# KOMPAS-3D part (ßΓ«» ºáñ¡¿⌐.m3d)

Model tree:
1. Эскиз:1
2. Операция выдавливания:1
     Расстояние 1 = 4.2; Расстояние 2 = 1.6
3. Эскиз:2
4. Операция выдавливания:2
     Расстояние 1 = 0.5; Расстояние 2 = 1.6
5. Эскиз:3
6. Операция выдавливания:6
     Расстояние 1 = 0.1; Расстояние 2 = 2.4
7. Эскиз:7
8. Операция выдавливания:7
     Расстояние 1 = 0.5; Расстояние 2 = 2.4
9. Эскиз:8
10. Операция выдавливания:8
     Расстояние 1 = 4; Расстояние 2 = 2.4
11. Эскиз:9
12. Операция выдавливания:9
     Расстояние 1 = 5; Расстояние 2 = 2.4
13. Скругление:5
     Радиус = 1.5
14. Скругление:6
     Радиус = 0.2
15. Эскиз:10
16. Операция выдавливания:10
     Расстояние 1 = 5; Расстояние 2 = 2
17. Эскиз:11
18. Вырезать элемент выдавливания:2
     Расстояние 1 = 0.5
19. Эскиз:12
20. Операция выдавливания:11
     Расстояние 1 = 0.5; Расстояние 2 = 2
21. Скругление:7
     Радиус = 0.2
22. Скругление:9
     Радиус = 1
23. Эскиз:14
24. Операция выдавливания:12
     Расстояние 1 = 0.5; Расстояние 2 = 2
25. Массив по концентрической сетке:1  (with: Операция выдавливания:12)  (labels: Экземпляр ( 1, 1 ); Экземпляр ( 1, 2 ); Экземпляр ( 1, 3 ); Экземпляр ( 1, 4 ))
     N 2 = 10; Шаг 2 = 360; Номер 2 = 1
26. Скругление:10
     Радиус = 0.1
27. Скругление:11
     Радиус = 0.1

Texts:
  Сплав АЛ8  ГОСТ 1583-93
